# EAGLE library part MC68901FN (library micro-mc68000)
68xxx PROCESSOR
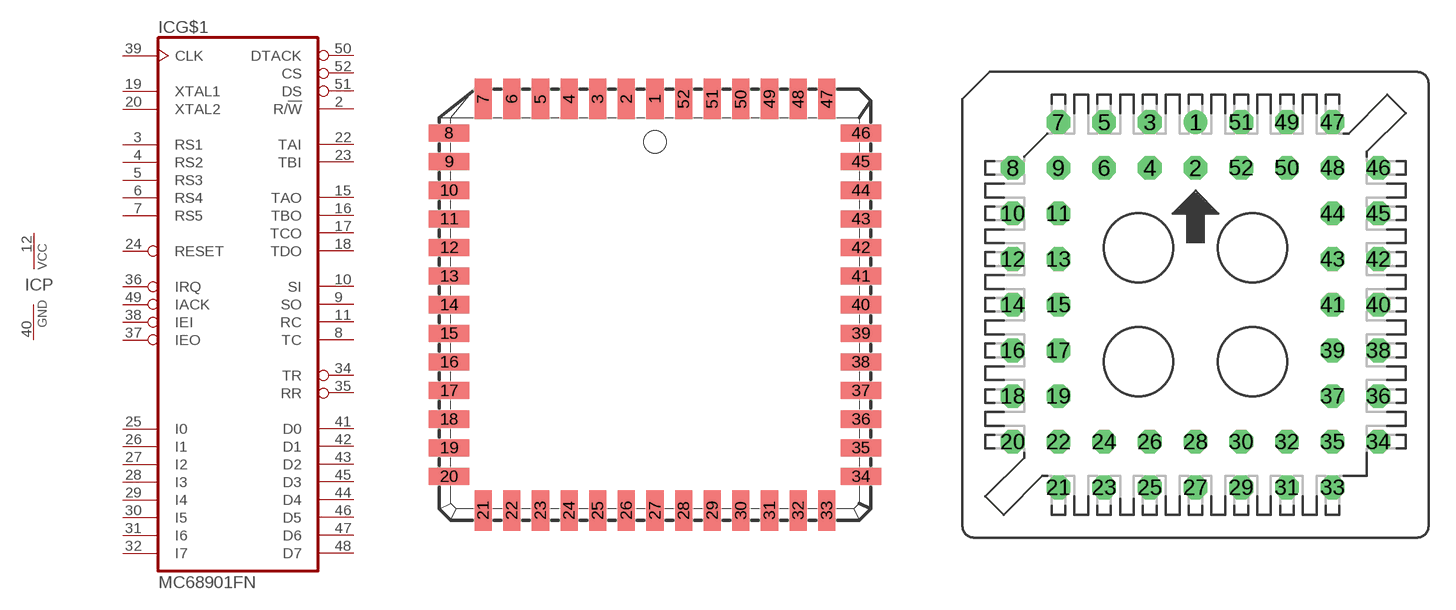
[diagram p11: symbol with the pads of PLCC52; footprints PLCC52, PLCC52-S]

Designator prefix IC; gates G$1=68901 P=PWRN

## MC68901FN (OC_FARNELL: unknown; OC_NEWARK: unknown)  [PLCC52]
2  G$1:R/!W  in
3  G$1:RS1  in
4  G$1:RS2  in
5  G$1:RS3  in
6  G$1:RS4  in
7  G$1:RS5  in
8  G$1:TC  in
9  G$1:SO  out
10  G$1:SI  in
11  G$1:RC  in
12  P:VCC  pwr
15  G$1:TAO  out
16  G$1:TBO  out
17  G$1:TCO  out
18  G$1:TDO  out
19  G$1:XTAL1  in
20  G$1:XTAL2  in
22  G$1:TAI  in
23  G$1:TBI  in
24  G$1:RESET  in
25  G$1:I0
26  G$1:I1
27  G$1:I2
28  G$1:I3
29  G$1:I4
30  G$1:I5
31  G$1:I6
32  G$1:I7
34  G$1:TR  out
35  G$1:RR  out
36  G$1:IRQ  out
37  G$1:IEO  out
38  G$1:IEI  in
39  G$1:CLK  in
40  P:GND  pwr
41  G$1:D0
42  G$1:D1
43  G$1:D2
44  G$1:D4
45  G$1:D3
46  G$1:D5
47  G$1:D6
48  G$1:D7
49  G$1:IACK  in
50  G$1:DTACK  out
51  G$1:DS  in
52  G$1:CS  in

## MC68901FN-SOC (OC_FARNELL: unknown; OC_NEWARK: unknown)  [PLCC52-S]
Pads as for PLCC52

## Footprint PLCC52 (pad centres in mm)
PLASTIC LEADED CHIP CARRIER square
smd 0.76 x 1.8: 1 0,9.13; 2 -1.27,9.13; 3 -2.54,9.13; 4 -3.81,9.13; 5 -5.08,9.13; 6 -6.35,9.13; 7 -7.62,9.13; 21 -7.62,-9.13; 22 -6.35,-9.13; 23 -5.08,-9.13; 24 -3.81,-9.13; 25 -2.54,-9.13; 26 -1.27,-9.13; 27 0,-9.13; 28 1.27,-9.13; 29 2.54,-9.13; 30 3.81,-9.13; 31 5.08,-9.13; 32 6.35,-9.13; 33 7.62,-9.13; 47 7.62,9.13; 48 6.35,9.13; 49 5.08,9.13; 50 3.81,9.13; 51 2.54,9.13; 52 1.27,9.13
smd 1.8 x 0.76: 8 -9.13,7.62; 9 -9.13,6.35; 10 -9.13,5.08; 11 -9.13,3.81; 12 -9.13,2.54; 13 -9.13,1.27; 14 -9.13,0; 15 -9.13,-1.27; 16 -9.13,-2.54; 17 -9.13,-3.81; 18 -9.13,-5.08; 19 -9.13,-6.35; 20 -9.13,-7.62; 34 9.13,-7.62; 35 9.13,-6.35; 36 9.13,-5.08; 37 9.13,-3.81; 38 9.13,-2.54; 39 9.13,-1.27; 40 9.13,0; 41 9.13,1.27; 42 9.13,2.54; 43 9.13,3.81; 44 9.13,5.08; 45 9.13,6.35; 46 9.13,7.62

## Footprint PLCC52-S (pad centres in mm)
PLCC Socked
drill 0.813 round: 1 0,10.16
drill 0.813 octagon: 2 0,7.62; 3 -2.54,10.16; 4 -2.54,7.62; 5 -5.08,10.16; 6 -5.08,7.62; 7 -7.62,10.16; 8 -10.16,7.62; 9 -7.62,7.62; 10 -10.16,5.08; 11 -7.62,5.08; 12 -10.16,2.54; 13 -7.62,2.54; 14 -10.16,0; 15 -7.62,0; 16 -10.16,-2.54; 17 -7.62,-2.54; 18 -10.16,-5.08; 19 -7.62,-5.08; 20 -10.16,-7.62; 21 -7.62,-10.16; 22 -7.62,-7.62; 23 -5.08,-10.16; 24 -5.08,-7.62; 25 -2.54,-10.16; 26 -2.54,-7.62; 27 0,-10.16; 28 0,-7.62; 29 2.54,-10.16; 30 2.54,-7.62; 31 5.08,-10.16; 32 5.08,-7.62; 33 7.62,-10.16; 34 10.16,-7.62; 35 7.62,-7.62; 36 10.16,-5.08; 37 7.62,-5.08; 38 10.16,-2.54; 39 7.62,-2.54; 40 10.16,0; 41 7.62,0; 42 10.16,2.54; 43 7.62,2.54; 44 7.62,5.08; 45 10.16,5.08; 46 10.16,7.62; 47 7.62,10.16; 48 7.62,7.62; 49 5.08,10.16; 50 5.08,7.62; 51 2.54,10.16; 52 2.54,7.62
